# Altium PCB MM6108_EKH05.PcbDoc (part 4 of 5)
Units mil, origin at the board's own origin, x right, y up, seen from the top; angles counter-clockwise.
Board outline 6023.62 x 3425.2 mil, 4 copper layers (Top Layer, Ground Plane, Middle Layer, Bottom Layer), stack 76.15 mil thick; 212 components, 163 nets, 749 pads, 1477 vias.
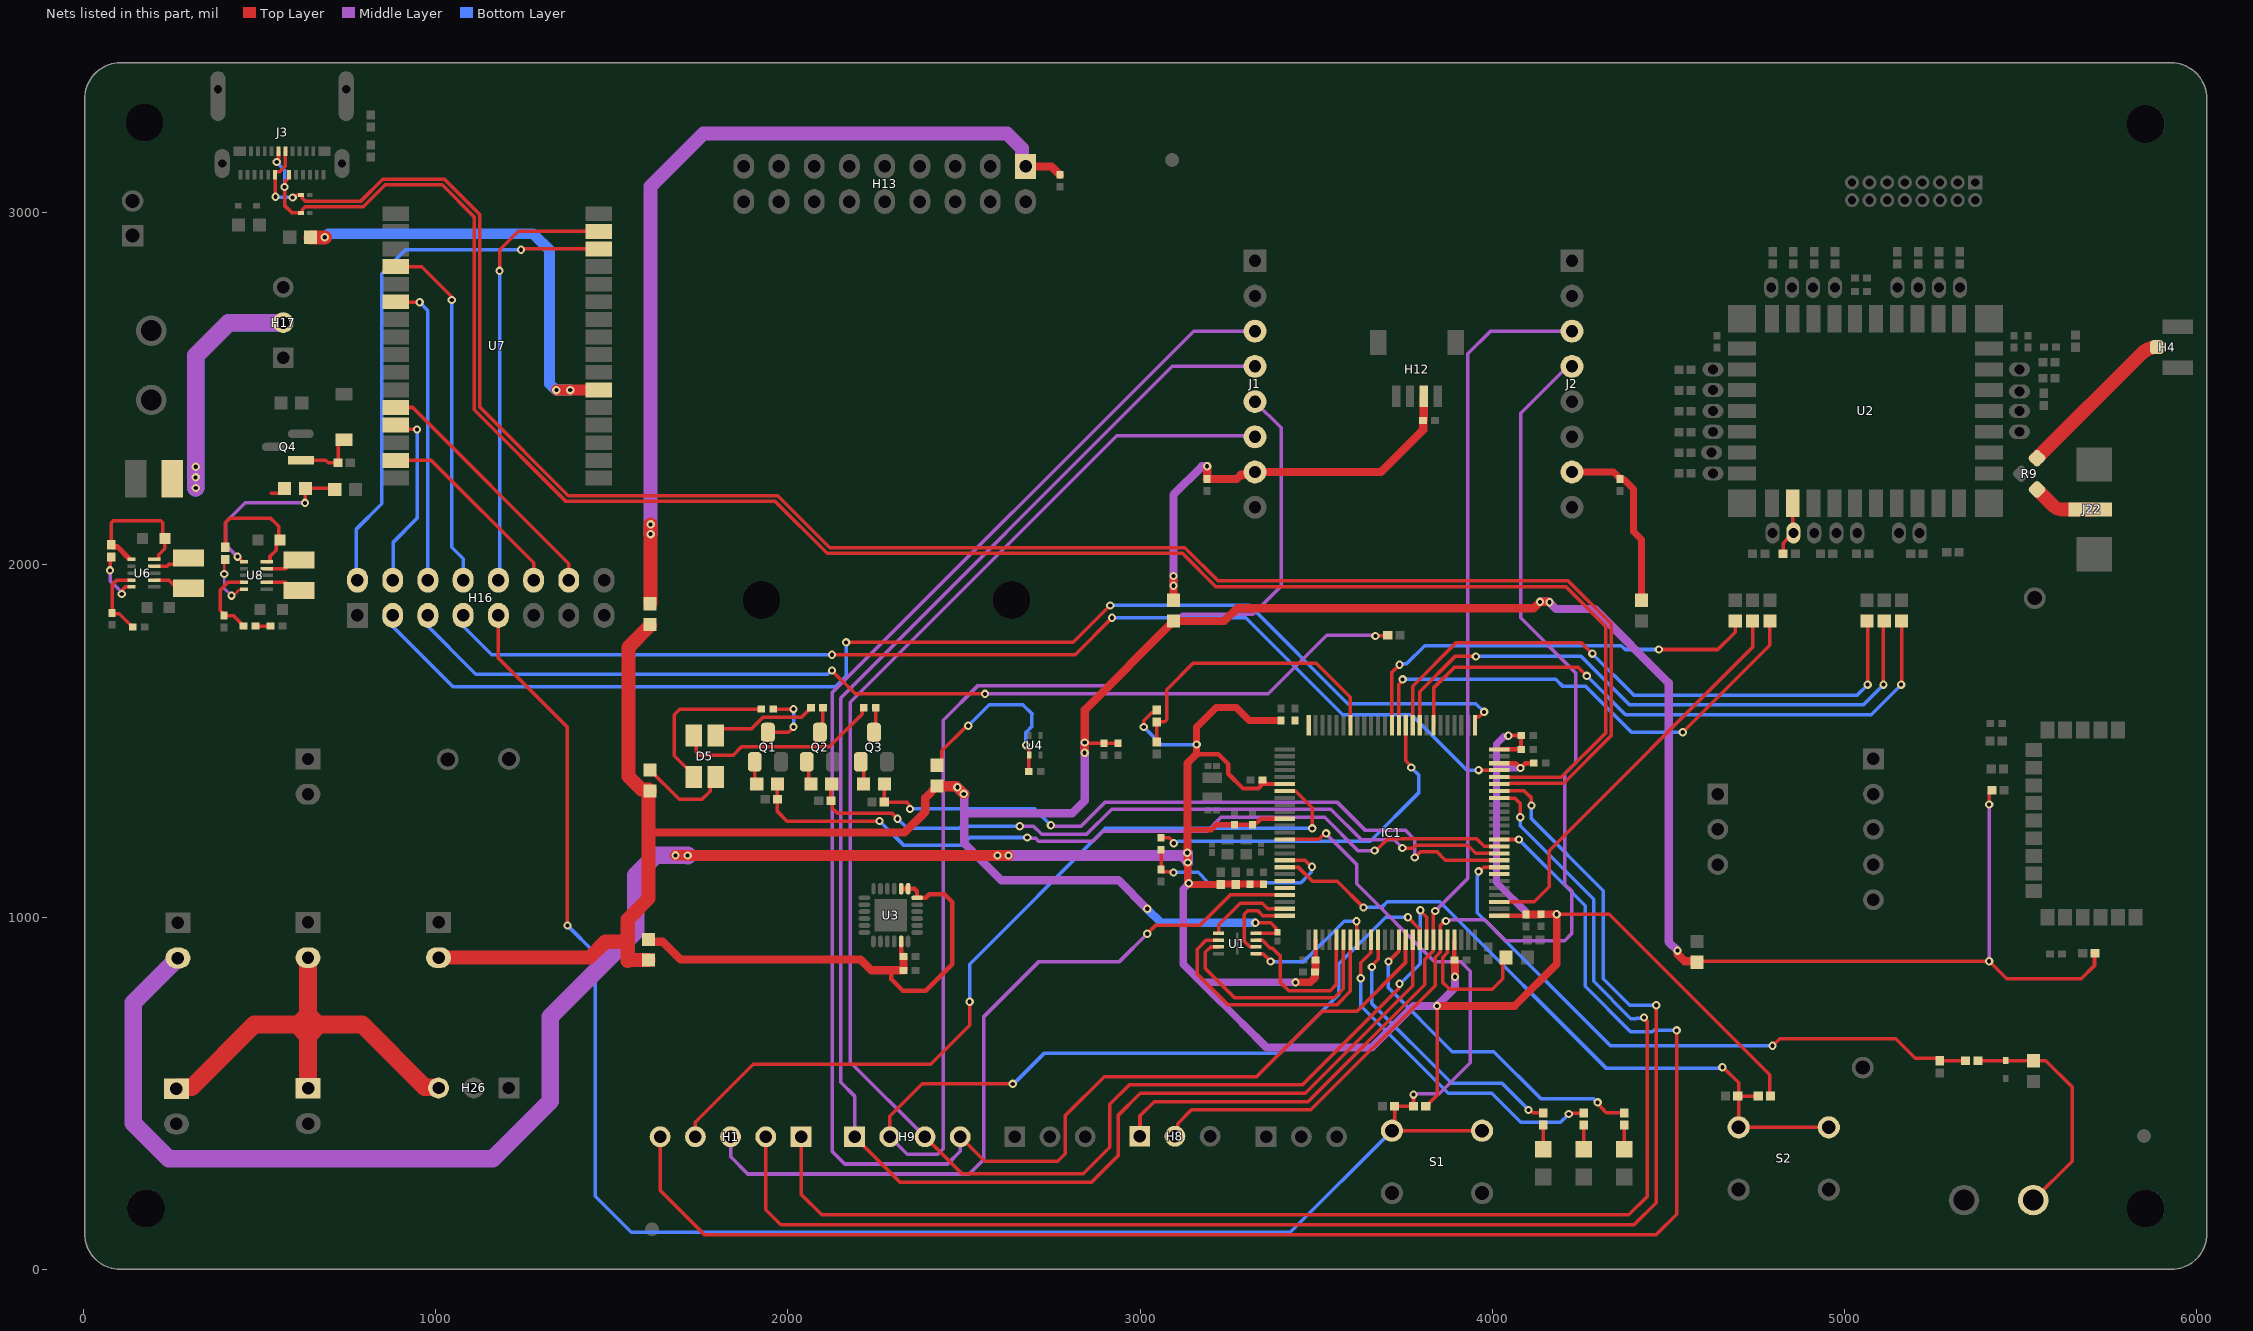
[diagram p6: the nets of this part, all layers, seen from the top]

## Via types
v1: diameter 23.62, hole 11.81, Top Layer to Bottom Layer, tented both sides, 1477 vias

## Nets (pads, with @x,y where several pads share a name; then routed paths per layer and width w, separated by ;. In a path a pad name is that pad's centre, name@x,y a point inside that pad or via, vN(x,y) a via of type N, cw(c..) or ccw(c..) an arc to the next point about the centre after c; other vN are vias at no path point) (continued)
NetC39_2: C39.2 R54.2 U4.3 | length 543.2
  Top Layer w10: R54.2@2423.23,1431.1 2436.63,1444.5 2436.63,1472.06 2501.06,1536.5 2501.31,1536.5 2508.12,1543.31 v1(2511.81,1543.31) ; v1(2675.64,1488.44) 2675.64,1484.75 2684.13,1476.26 2684.13,1461.54 U4.3@2685.04,1460.63 2683.46,1459.06 C39.2@2683.46,1413.39
  Bottom Layer w10: v1(2511.81,1543.31) 2571.77,1603.27 2666.61,1603.27 2692.79,1577.08 2692.79,1576.91 2692.66,1576.78 2692.66,1541.61 2685,1533.95 2685,1533.64 2675.64,1524.28 v1(2675.64,1488.44)
NetC45_2: C45.2 H13.1 R55.2 | length 2506.4
  Top Layer w23.62: H13.1@2674.41,3131.5 2674.73,3131.17 2748.03,3131.17 C45.2@2771.65,3107.55
  Top Layer w40: v1(1610,2115) 1610,1891.97 R55.2@1610.24,1891.73
  Middle Layer w40: v1(1610,2087.44) v1(1610,2115) 1610,3074.57 1759.84,3224.41 1908.23,3224.41 2622.05,3224.41 2664.88,3181.57 2664.88,3141.02 H13.1@2674.41,3131.5
NetC46_2: C46.2 C48.2 H12.3 J1.7 R61.2 | length 1261.6
  Top Layer w23.62: R61.2@3094.49,1899.61 v1(3094.49,1940.94) v1(3094.49,1968.5) ; v1(3190,2280) 3190,2244.8 C46.2@3188.98,2243.77 3273.77,2243.77 3285.67,2255.67 3317.67,2255.67 J1.7@3325.59,2263.58 3683.58,2263.58 3803,2383 C48.2@3803,2410 3805.28,2412.28 H12.3@3805.28,2479
  Middle Layer w23.62: v1(3094.49,1940.94) v1(3094.49,1968.5) 3094.49,2199.49 3175,2280 v1(3190,2280)
NetC47_2: C47.2 J2.7 R60.1 | length 521.1
  Top Layer w20: J2.7@4225.59,2263.58 4343.39,2263.58 4362.2,2244.77 C47.2@4362.2,2243.77 4362.2,2242.77 4372.83,2242.77 4400,2215.6 4400,2095 4423.23,2071.77 R60.1@4423.23,1899.61
NetD1_A: D1.A R4.2 | length 68.9
  Top Layer w10: D1.A@4374.02,340.94 R4.2@4374.02,409.84
NetD2_A: D2.A R5.2 | length 68.9
  Top Layer w10: D2.A@4258.86,340.94 R5.2@4258.86,409.84
NetD3_A: D3.A R6.2 | length 68.9
  Top Layer w10: D3.A@4143.7,340.94 R6.2@4143.7,409.84
NetD4_K: D4.K H11.2 R51.1 R52.1 | length 665.2
  Top Layer w10: R51.1@5377.95,592.52 D4.K@5456.69,592.52 R52.1@5535.43,592.52 5570.87,592.52 5645.67,517.72 5645.67,307.09 H11.2@5535.43,196.85
NetD5_1: D5.1 R59.1 | length 454.1
  Top Layer w10: D5.1@1732.28,1397.65 1732.28,1405.53 1713.65,1424.15 1711.64,1424.15 1677.17,1458.62 1677.17,1574.8 1692.91,1590.55 R59.1@1923.62,1590.55
NetD5_2: D5.2 R56.2 | length 280.6
  Top Layer w10: R56.2@1621.97,1431.02 R56.2@1608.27,1417.32 1690.94,1334.65 1755.91,1334.65 1778.92,1357.67 1778.92,1381.31 D5.2@1795.27,1397.65
NetD5_3: D5.3 R58.1 | length 303.3
  Top Layer w10: D5.3@1795.27,1515.76 1795.27,1516.81 1813.89,1535.43 1896.96,1535.43 1928.45,1566.93 2037.8,1566.93 R58.1@2065.35,1594.49
NetD5_4: D5.4 R57.1 | length 591.7
  Top Layer w10: D5.4@1732.28,1515.76 1740,1508.04 1740,1470 1750,1460 1844.66,1460 1868.14,1483.48 2117.34,1483.48 2210.71,1576.85 2210.71,1589.91 R57.1@2215.28,1594.49
NetD6_A: D6.A Q4.1 R75.1 | length 184.2
  Top Layer w10: Q4.1@616.82,2297.6 687.4,2297.6 695,2290 R75.1@722.68,2290 722.68,2342.52 735.59,2355.43 D6.A@740,2355.43
NetH4_1: H4.1 R9.C | length 467.9
  Top Layer w39: R9.C@5545.89,2303.03 5843.39,2600.53 cw(c5885.83,2558.1) H4.1@5885.83,2618.11
NetH16_2: H16.2 U7.30 | length 1548.6
  Top Layer w10: v1(1242.26,2894.52) 1244.59,2896.85 U7.30@1462.76,2896.85
  Bottom Layer w10: H16.2@775,1953.09 775,2101.77 846.46,2173.23 846.46,2826.77 914.21,2894.52 v1(1242.26,2894.52)
NetH16_4: H16.4 U7.13 | length 522.2
  Top Layer w10: U7.13@886.38,2396.85 898.71,2384.52 v1(946.95,2384.52)
  Bottom Layer w10: H16.4@877.76,1956.69 880,1958.94 880,2065 946.95,2131.95 v1(946.95,2384.52)
NetH16_5: H16.5 R3.1 | length 2924.2
  Top Layer w10: v1(2125,1700) 2191.14,1633.86 v1(2559.06,1633.86) ; v1(3667.43,1798.25) 3668.3,1799.13 3701.8,1799.13 R3.1@3702.68,1800
  Middle Layer w10: v1(2559.06,1633.86) 3363.86,1633.86 3530,1800 3665.68,1800 v1(3667.43,1798.25)
  Bottom Layer w10: H16.5@952.76,1856.69 952.76,1850.79 965.26,1838.29 1113.54,1690 2112.33,1690 2122.33,1700 v1(2125,1700)
NetH16_6: H16.6 U7.6 | length 867
  Top Layer w10: U7.6@886.38,2746.85 887.71,2745.51 v1(954.28,2745.51)
  Bottom Layer w10: v1(954.28,2745.51) 977.76,2722.04 H16.6@977.76,1956.69
NetH16_8: H16.8 U7.4 | length 1017.4
  Top Layer w10: U7.4@886.38,2846.85 960.24,2846.85 1047.24,2759.84 v1@1047.24,2748.03
  Bottom Layer w10: v1(1045.28,2751.97) 1045.28,2049.72 1077.76,2017.24 H16.8@1077.76,1956.69
NetH16_10: H16.10 U7.31 | length 1242.1
  Top Layer w10: v1(1181.1,2834.65) 1182.19,2835.73 1182.19,2894.78 1234.25,2946.85 U7.31@1462.76,2946.85
  Bottom Layer w10: H16.10@1177.76,1956.69 1181.1,1960.04 v1(1181.1,2834.65)
NetH16_12: H16.12 U7.15 | length 561
  Top Layer w10: U7.15@886.38,2296.85 986.61,2296.85 1277.76,2005.71 H16.12@1277.76,1956.69
NetH16_14: H16.14 U7.12 | length 721.8
  Top Layer w10: U7.12@886.38,2446.85 934.35,2446.85 1377.76,2003.45 H16.14@1377.76,1956.69
NetIC1_46: IC1.46 L1.2 | length 382.7
  Top Layer w10: IC1.46@3872.05,935.51 3872.05,898.81 3858.27,885.04 3858.27,814.96 3878.23,795 3999.72,795 4029.53,824.8 4029.53,877.36 L1.2@4037.99,885.83
NetJ22_1: J22.1 R9.B | length 173.1
  Top Layer w39: R9.B@5545.89,2213.95 5546.02,2213.82 5590.97,2168.87 ccw(c5618.52,2196.48) 5618.52,2157.48 J22.1@5697.25,2157.48
NetL3_1: L3.1 U6.9 | length 68.1
  Top Layer w10: U6.9@214.06,1996.38 237.56,1996.38 242.48,2001.3 L3.1@280.08,2001.3
NetL3_2: L3.2 U6.7 | length 84
  Top Layer w10: U6.7@201.34,1957.01 241.69,1957.01 254.49,1944.21 L3.2@280.08,1944.21
NetL4_1: L4.1 U8.9 | length 92.3
  Top Layer w10: U8.9@520.43,1989.69 574.57,1989.68 583.43,1998.54 L4.1@609.02,1998.54
NetL4_2: L4.2 U8.7 | length 92.3
  Top Layer w10: U8.7@520.43,1950.32 574.57,1950.32 583.43,1941.46 L4.2@609.02,1941.46
NetQ1_D: Q1.D R59.2 | length 187.7
  Top Layer w10: Q1.D@1942.93,1524.37 2000.75,1524.37 2008.94,1532.56 2008.94,1532.81 2015.75,1539.62 v1(2015.75,1540.12) ; R59.2@1958.27,1590.55 v1(2015.75,1590.55)
  Bottom Layer w10: v1(2015.75,1540.12) v1(2015.75,1590.55)
NetQ1_G: Q1.G R62.2 | length 65.4
  Top Layer w10: Q1.G@1905.53,1440.94 1905.53,1383.84 R62.2@1911.42,1377.95
NetQ2_D: Q2.D R58.2 | length 73.7
  Top Layer w10: Q2.D@2090.55,1524.37 2099.21,1533.03 R58.2@2099.21,1594.49
NetQ2_G: Q2.G R63.2 | length 70.5
  Top Layer w10: R63.2@2059.06,1383.86 Q2.G@2059.06,1435.04
  Top Layer w23.62: Q2.G@2053.15,1440.94 Q2.G@2059.06,1435.04 ; R63.2@2059.06,1383.86 R63.2@2064.96,1377.95 ; R63.2@2067.02,1379.83 R63.2@2068.9,1377.95
NetQ3_D: Q3.D R57.2 | length 72.4
  Top Layer w10: Q3.D@2244.11,1524.37 2249.61,1529.87 R57.2@2249.61,1594.49
NetQ3_G: Q3.G R64.2 | length 74.6
  Top Layer w10: Q3.G@2206.71,1440.94 2214.57,1433.09 R64.2@2214.57,1377.95 R64.2@2220.47,1372.05
NetR10_1: R10.1 R12.1 U8.1 | length 525.6
  Top Layer w10: v1(629,2176) 629,2216.16 R10.1@630.01,2217.17 704.3,2217.17 R12.1@704.47,2217 ; U8.1@448.66,2009.45 U8.1@448.66,2011.34 ; U8.1@448.66,2009.45 U8.1@448.74,2009.37 ; U8.1@448.66,2009.45 U8.1@448.74,2009.37 ; U8.1@448.66,2009.45 U8.1@448.66,2011.34 ; U8.1@448.66,2011.34 437,2023 U8.1@448.66,2011.34 ; U8.1@448.74,2009.37 U8.1@455.47,2009.37 U8.1@448.74,2009.37
  Middle Layer w10: v1(437.24,2023.54) 404,2056.78 404,2121 459,2176 v1(629,2176)
NetR30_2: pad.31@4854.33,2090.55 R30.2 U2.10 | length 157.7
  Top Layer w10: R30.2@4825.2,2031.5 4825.2,2061.42 4838.59,2074.81 4840.47,2074.81 4854.33,2088.67 pad.31@4854.33,2090.55 4852.36,2092.52 U2.10@4852.36,2175.2
NetR68_2: R68.2 U6.5 | length 156.7
  Top Layer w10: v1(75.35,1984.57) 75.35,2018.43 R68.2@79.29,2022.36 ; v1(108.82,1917.64) 111.43,1920.24 111.43,1929.98 118.77,1937.32 U6.5@129.57,1937.32
  Middle Layer w10: v1(75.35,1984.57) 75.35,1954.79 108.18,1921.96 v1@108.18,1915.46
NetR71_2: R71.2 R72.1 U6.4 | length 216.3
  Top Layer w10: U6.4@136.38,1957.01 95.04,1957.01 81.26,1943.23 R72.1@81.26,1863.77 84.15,1860.89 102.02,1860.89 132.95,1829.96 134.13,1829.96 139.76,1824.33 R71.2@139.77,1823.15
NetR73_1: R73.1 U7.22 | length 1268.2
  Top Layer w31: v1(1342.52,2496.06) v1(1381.89,2496.06) 1461.97,2496.06 U7.22@1462.76,2496.85
  Top Layer w40: R73.1@644.53,2930 v1(685,2930)
  Bottom Layer w31: v1(685,2930) 695,2940 1276.54,2940 1322.83,2893.7 1322.83,2514.22 1340.99,2496.06 v1(1342.52,2496.06) v1(1381.89,2496.06)
NetR74_2: R74.2 U8.5 | length 155.3
  Top Layer w8: v1(399.49,1974.14) 399.49,2012.83 R74.2@402.32,2015.67 ; v1(420.04,1912.84) 423.03,1915.83 429.05,1915.83 442.93,1929.71 454.55,1929.71 U8.5@455.47,1930.63
  Middle Layer w8: v1(399.49,1974.14) 399.49,1933.39 v1(420.04,1912.84)
NetR76_2: R76.2 R84.1 | length 42.9
  Top Layer w10: R84.1@488.22,1826.23 R76.2@531.17,1826.23
NetR77_1: R77.1 R84.2 U8.4 | length 226.6
  Top Layer w10: U8.4@455.47,1950.32 410.27,1950.32 388.54,1928.59 388.54,1870.79 397.48,1861.86 397.48,1860.67 403.11,1855.04 404.29,1855.04 426.65,1855.04 448.58,1833.12 448.58,1831.86 R84.2@459.41,1821.03
PA0: H1.3 IC1.22 | length 2215.6
  Top Layer w10: v1(3019.69,952.76) 3043.31,976.38 3169.29,976.38 3255.91,1062.99 IC1.22@3409.92,1062.99
  Middle Layer w10: H1.3@1837.01,376.69 1837.01,320.09 1886.26,270.84 2514.94,270.84 2555.12,311.02 2555.12,716.54 2712.6,874.02 2940.94,874.02 v1(3019.69,952.76)
PA9: H1.1 IC1.68 | length 3968
  Top Layer w10: H1.1@2037.01,376.69 2037.01,213.61 2095.56,155.06 4387.34,155.06 4440,207.72 4440,702.33 4430,712.33 v1(4430,715) ; IC1.68@4019.21,1338.58 4020.12,1337.68 4063.9,1337.68 4078.74,1322.83 v1@4078.74,1284.32
  Bottom Layer w10: v1(4078.74,1283.46) 4078.74,1259.84 4287.4,1051.18 4287.4,817.6 4392.95,712.05 4408.19,712.05 4408.53,712.39 4427.39,712.39 v1(4430,715)
PA10: H1.2 IC1.69 | length 4217.7
  Top Layer w10: H1.2@1937.01,376.69 1937.01,169.29 1979.38,126.92 4401.92,126.92 4464.54,189.54 4464.54,749.54 v1(4465,750) ; IC1.69@4019.21,1358.27 4090.55,1358.27 4110.63,1338.19 v1(4110.63,1316.83)
  Bottom Layer w10: v1(4110.63,1316.83) 4110.63,1279.13 4314.96,1074.8 4314.96,825.04 4390,750 v1(4465,750)
PC13: H1.4 IC1.7 | length 2396.4
  Top Layer w10: H1.4@1737.01,376.69 1737.01,418.11 1901.57,582.68 2405.51,582.68 2515.75,692.91 v1(2515.75,759.84) ; IC1.7@3409.92,1358.27 3410.83,1357.36 3441.64,1357.36 3488.19,1310.81 v1(3488.19,1251.97)
  Bottom Layer w10: v1(2515.75,759.84) 2515.75,866.35 2901.37,1251.97 v1(3488.19,1251.97)
PD10: IC1.57
PD11: C36.1 IC1.58 R51.2 | length 1758.7
  Top Layer w10: v1(3960.63,1129.92) 3963.37,1129.92 3975.18,1141.73 IC1.58@4019.21,1141.73 ; v1(4795,635) 4815,655 5144.62,655 5199.8,599.82 5262.48,599.82 C36.1@5269.69,592.61 ; C36.1@5269.69,592.52 R51.2@5343.31,592.52
  Bottom Layer w10: v1(3960.63,1129.92) 3958.02,1127.31 3958.02,1118.06 3957.21,1117.25 3957.21,1012.79 4335,635 v1(4795,635)
PD15: H1.5 IC1.62 | length 4524.8
  Top Layer w10: H1.5@1637.01,400.68 1637.01,224.1 1762.18,98.92 4465.06,98.92 4522.81,156.67 v1(4522.81,678.54) ; IC1.62@4019.21,1220.47 v1(4074.8,1220.47)
  Bottom Layer w10: v1(4074.8,1220.47) 4262.97,1032.31 4262.97,803.96 4391.93,675 4453.76,675 4457.3,678.54 v1(4522.81,678.54)
PH3-BOOT0: IC1.94 R7.1 R8.1 | length 832.9
  Top Layer w10: R8.1@3047.24,1509.45 R7.1@3047.24,1554.33 ; R7.1@3047.24,1553.54 R7.1@3047.24,1554.33 ; IC1.94@3596.46,1544.8 3596.46,1624.02 3500,1720.47 3149.61,1720.47 3074.8,1645.67 3074.8,1560.19 3068.95,1554.33 R7.1@3047.24,1554.33
SDMMC2_CLK: IC1.87 R31.1 | length 1409.8
  Top Layer w10: IC1.87@3734.25,1544.8 3734.25,1660.57 3745,1671.31 v1(3745,1675) ; v1(4540,1525) 4787.4,1772.4 R31.1@4787.4,1840.55
  Bottom Layer w10: v1(3745,1675) 4180,1675 4200.12,1654.88 4264.85,1654.88 4394.73,1525 v1(4540,1525)
SDMMC2_CMD: IC1.88 R32.1 | length 1212.4
  Top Layer w10: IC1.88@3714.57,1544.8 3714.57,1694.88 v1(3736.22,1716.54) ; v1(4472.44,1759.84) 4639.84,1759.84 4688.98,1808.98 R32.1@4688.98,1840.55
  Bottom Layer w10: v1(3736.22,1716.54) 3738.83,1719.14 3755.93,1719.14 3807.63,1770.84 4365.89,1770.84 4376.89,1759.84 v1(4472.44,1759.84)
SDMMC2_D0: IC1.53 R33.1 | length 1153
  Top Layer w10: IC1.53@4019.21,1043.31 4118.11,1043.31 4161.17,1086.36 4161.17,1188.72 4738.19,1765.75 R33.1@4738.19,1840.55
SENSORS_SPI_CLK: H9.1 IC1.41 J1.4 | length 4893.7
  Top Layer w10: H9.1@2188.88,376.69 2317.54,248.03 2862.2,248.03 2937.01,322.83 2937.01,437.01 3000,500 3468.5,500 3773.62,805.12 IC1.41@3773.62,935.51
  Middle Layer w10: H9.1@2188.88,376.69 2188.88,492.22 2149.61,531.5 2149.61,1622.05 3091.14,2563.58 J1.4@3325.59,2563.58
SENSORS_SPI_CS: H9.4 IC1.40 J1.3 | length 5016.4
  Top Layer w10: H9.4@2488.88,376.69 2558.48,307.09 2765.8,307.09 2781.54,322.83 2787.4,328.69 2787.4,437.01 2897.64,547.24 3330.04,547.24 3515.08,732.28 3614.17,732.28 3753.03,871.14 3753.03,934.61 IC1.40@3753.94,935.51
  Middle Layer w10: H9.4@2488.88,376.69 2488.88,335.33 2452.76,299.21 2161.42,299.21 2125.98,334.65 2125.98,1637.8 3151.77,2663.58 J1.3@3325.59,2663.58
SENSORS_SPI_MISO: H9.2 IC1.42 J1.5 | length 4954.8
  Top Layer w10: H9.2@2288.88,376.69 2288.88,434.55 2381.12,526.79 v1(2638.08,526.79) ; v1(3759.7,999.66) 3759.97,999.66 3792.4,967.23 3792.4,936.42 IC1.42@3793.31,935.51
  Middle Layer w10: H9.2@2288.88,376.69 2338.8,326.77 2425.2,326.77 2440.94,342.52 2440.94,1559.06 2539.37,1657.48 2917.32,1657.48 3119.84,1860 3320,1860 3400,1940 3400,2389.17 J1.5@3325.59,2463.58
  Bottom Layer w10: v1@2641.73,527.56 2728.35,614.17 3397.64,614.17 3562.99,779.53 3562.99,866.14 3696.51,999.66 v1(3759.7,999.66)
SENSORS_SPI_MOSI: H9.3 IC1.43 J1.6 | length 4801.9
  Top Layer w10: H9.3@2388.88,376.69 2493.92,271.65 2838.58,271.65 2913.39,346.46 2913.39,468.39 2968.62,523.62 3459.87,523.62 3733.61,797.37 3733.61,808.42 v1(3736.22,811.02) ; v1(3795.28,1019.68) 3795.28,1017.2 3812.99,999.48 IC1.43@3812.99,935.51
  Middle Layer w10: H9.3@2388.88,376.69 2177.17,588.41 2177.17,1610.24 2933.07,2366.14 3323.03,2366.14 J1.6@3325.59,2363.58
  Bottom Layer w10: v1(3736.22,811.02) 3738.41,811.02 3795.28,867.89 v1(3795.28,1019.68)
SENSORS_UART_RX: H8.1 IC1.44 J2.3 | length 3186
  Top Layer w10: H8.1@2998.43,377.95 2999.3,378.83 2999.3,436.31 3039.37,476.38 3476.15,476.38 3807.89,808.12 3807.89,879.92 3831.77,903.79 3831.77,934.61 IC1.44@3832.68,935.51 3831.8,936.39 3831.8,1008.9 3837.51,1014.62 v1(3837.51,1017.31)
  Middle Layer w10: v1(3837.51,1017.31) 3930,1109.79 3930,2599.29 3994.29,2663.58 J2.3@4225.59,2663.58
SENSORS_UART_TX: H8.2 IC1.45 J2.4 | length 3290.3
  Top Layer w10: H8.2@3098.43,377.95 3106.13,385.66 3106.13,413.22 3145.67,452.76 3484.25,452.76 3837,805.5 3837,886.39 3851.46,900.85 3851.46,934.61 IC1.45@3852.36,935.51 3852.36,976.85 3864.51,989 v1(3867.6,989)
  Middle Layer w10: v1(3867.6,989) 3870.2,991.61 3879.75,991.61 3880.27,992.13 3977.87,992.13 4036.93,933.07 4204.72,933.07 4224.41,952.76 4224.41,1074.8 4205.54,1093.68 4205.54,1407.26 4236.22,1437.94 4236.22,1693.3 4080,1849.52 4080,2430.39 4213.19,2563.58 J2.4@4225.59,2563.58 J2.4@4231.69,2563.58
STATUS_LED_B: IC1.36 R6.1 | length 803.6
  Top Layer w10: v1(3657.48,858.27) 3657.48,861.95 3676.1,880.58 3676.1,934.61 IC1.36@3675.2,935.51 ; v1(4102.36,452.76) 4106.05,452.76 4114.32,444.49 R6.1@4143.7,444.49
  Bottom Layer w10: v1(3657.48,858.27) 3657.48,754.79 3884.21,528.06 4027.06,528.06 v1(4102.36,452.76)
STATUS_LED_G: IC1.35 R5.1 | length 980.8
  Top Layer w10: v1(3625.98,826.77) 3625.98,870.08 3654.61,898.7 3654.61,934.61 IC1.35@3655.51,935.51 ; v1(4216.54,440.94) 4218.31,442.72 4257.09,442.72 R5.1@4258.86,444.49
  Bottom Layer w10: v1(3625.98,826.77) 3625.98,748.03 3874.02,500 3997.87,500 4080.55,417.32 4192.91,417.32 v1(4216.54,440.94)
STATUS_LED_R: IC1.39 R4.1 | length 967.7
  Top Layer w10: v1(3704.72,874.02) 3733.35,902.64 3733.35,934.61 IC1.39@3734.25,935.51 ; v1(4298.56,474.16) 4298.56,470.48 4315.31,453.73 4315.31,452.4 4323.23,444.49 R4.1@4374.02,444.49
  Bottom Layer w10: v1(3704.72,874.02) 3704.72,799.21 3885.83,618.11 4003.94,618.11 4137.05,485 4285.9,485 4296.73,474.16 v1(4298.56,474.16)
STM_NRST: C19.1 H16.9 IC1.14 R2.2 S1.1 S1.2 | length 5799
  Top Layer w10: H16.9@1177.76,1865.03 1177.76,1735.63 1374.02,1539.37 v1(1374.02,976.38) ; IC1.14@3409.92,1220.47 3410.83,1221.38 3507.53,1221.38 3523.96,1237.81 v1(3527.65,1237.81) ; v1(3775.59,496.06) 3775.79,495.87 3775.79,462.8 R2.2@3775.98,462.6 C19.1@3722.05,462.6 3722.05,401.18 S1.2@3714.57,393.7 S1.1@3970.47,393.7
  Middle Layer w10: v1(3527.65,1237.81) 3527.65,1236.13 3614.17,1149.61 3614.17,1094.49 3834.65,874.02 3909.45,874.02 3937.01,846.46 3937.01,586.61 3849.06,498.67 3778.2,498.67 v1(3775.59,496.06)
  Bottom Layer w10: v1(1374.02,976.38) 1452.76,897.64 1452.76,207.24 1554.62,105.38 3426.25,105.38 S1.2@3714.57,393.7
STM_QSPI_CLK: IC1.25 U1.6 | length 240.6
  Top Layer w10: U1.6@3328.54,915.35 3312,915.35 3295.28,932.08 3295.28,1007.79 3305.45,1017.97 3334.2,1017.97 3347.98,1004.19 3409.67,1004.19 IC1.25@3409.92,1003.94
STM_QSPI_CS: IC1.24 U1.1 | length 242.8
  Top Layer w10: U1.1@3222.64,954.72 3222.64,978.54 3283.46,1039.37 3346.46,1039.37 3362.2,1023.62 IC1.24@3409.92,1023.62
STM_QSPI_IO0: IC1.33 U1.5 | length 394.5
  Top Layer w10: U1.5@3328.54,895.67 3348.43,895.67 v1(3370.08,874.02) ; v1(3614.17,988.19) 3615.24,987.13 3615.24,936.42 IC1.33@3616.14,935.51
  Bottom Layer w10: v1@3370.94,874.02 3464.57,874.02 3578.74,988.19 v1(3614.17,988.19)
STM_QSPI_IO1: IC1.32 U1.2 | length 775.1
  Top Layer w10: U1.2@3222.64,935.04 3222.56,934.96 3187.22,934.96 3161.42,909.16 3161.42,838.58 3248.03,751.97 3559.06,751.97 3596.46,789.37 IC1.32@3596.46,935.51
STM_QSPI_IO2: IC1.31 U1.3 | length 664.6
  Top Layer w10: 3206.1,915.35 3206.02,915.28 ; U1.3@3222.64,915.35 3222.56,915.28 3206.02,915.28 ; IC1.31@3576.77,935.51 3576.77,797.24 3551.18,771.65 3267.72,771.65 3185.04,854.33 3185.04,900.04 3200.28,915.28 3206.02,915.28
STM_QSPI_IO3: IC1.30 U1.7 | length 465.7
  Top Layer w10: U1.7@3328.54,935.04 3328.62,934.96 3345.94,934.96 3369.07,911.83 3375.57,911.83 3396.88,890.52 3396.88,815.71 3421.26,791.34 3539.37,791.34 3557.09,809.06 IC1.30@3557.09,935.51
STM_SPI2_CLK: IC1.82 R41.2 | length 1729.1
  Top Layer w10: IC1.82@3832.68,1544.8 3832.7,1650.67 3890.94,1708.91 4243.84,1708.91 v1(4267.72,1685.04) ; v1(5160,1660) 5161.42,1661.42 R41.2@5161.42,1840.55
  Bottom Layer w10: v1(4267.72,1685.04) 4377.76,1575 5075,1575 v1(5160,1660)
STM_SPI2_MISO: IC1.84 R43.2 | length 1715.6
  Top Layer w10: IC1.84@3793.31,1544.8 3793.33,1639.78 3893.7,1740.16 v1(3952.76,1740.16) ; v1(5110,1660) 5110,1838.35 R43.2@5112.2,1840.55
  Bottom Layer w10: v1(3952.76,1740.16) 4251.97,1740.16 4389.76,1602.36 5052.36,1602.36 v1(5110,1660)
STM_SPI2_MOSI: IC1.85 R42.2 | length 1709.2
  Top Layer w10: IC1.85@3773.64,1544.82 3773.64,1655.53 3897.64,1779.53 4251.97,1779.53 v1(4283.46,1748.03) ; R42.2@5062.99,1840.55 5065,1838.54 v1(5065,1660)
  Bottom Layer w10: v1(4283.46,1748.03) 4401.57,1629.92 5034.92,1629.92 v1(5065,1660)
SWD_CLK: H16.3 IC1.76 | length 3542.1
  Top Layer w10: v1(2165,1780) 2810,1780 v1(2915,1885) ; IC1.76@3950.79,1544.8 3950.79,1567.93 3951.69,1568.84 3962.54,1568.84 v1(3976.38,1582.68)
  Bottom Layer w10: H16.3@852.76,1856.69 852.76,1850.79 1049.17,1654.38 2134.38,1654.38 2165,1685 v1(2165,1780) ; v1(2915,1885) 3310,1885 3588.7,1606.3 3952.76,1606.3 v1(3976.38,1582.68)
SWD_DIO: H16.7 IC1.72 | length 3231.3
  Top Layer w10: v1(2125,1745) 2815,1745 v1(2920,1850) ; v1(3960.63,1417.32) IC1.72@4019.21,1417.32
  Bottom Layer w10: H16.7@1053.94,1849.61 1158.54,1745 v1(2125,1745) ; v1(2920,1850) 3300,1850 3575.2,1574.8 3770.2,1574.8 3927.68,1417.32 v1(3960.63,1417.32)
TIM4_CH1: IC1.59 R64.1 R67.2 | length 1971.9
  Top Layer w10: R64.1@2273.62,1377.95 2273.23,1377.56 R67.2@2273.23,1326.77 2336.51,1326.77 2343.85,1319.43 2343.85,1309.69 v1(2346.46,1307.09) ; v1(3779.53,1169.29) 3796.48,1186.24 3841.32,1186.24 3866.14,1161.42 IC1.59@4019.21,1161.42
  Middle Layer w10: v1(2746.32,1260.74) 2748.48,1258.59 2832.61,1258.59 2900.79,1326.77 3558.42,1326.77 3637.9,1247.29 3752.4,1247.29 3779.53,1220.16 v1(3779.53,1169.29)
  Bottom Layer w10: v1(2346.46,1307.09) 2699.98,1307.09 v1(2746.32,1260.74)
TIM4_CH2: IC1.60 R63.1 R66.2 | length 2088.7
  Top Layer w10: R63.1@2124.02,1377.95 2122.05,1375.98 R66.2@2122.05,1330.71 2125.64,1327.12 2125.64,1309.36 2139.47,1295.53 2295.02,1295.53 v1(2311.02,1279.53) ; v1(3744.09,1196.19) 3775.19,1196.19 3783,1204 3929.86,1204 3952.76,1181.1 IC1.60@4019.21,1181.1
  Middle Layer w10: v1(2657.88,1258.19) 2696.81,1258.19 2720,1235 2847.59,1235 2918.86,1306.28 3541.01,1306.28 3627.95,1219.34 3721.61,1219.34 3744.09,1196.85 v1(3744.09,1196.19)
  Bottom Layer w10: v1(2311.02,1279.53) 2338.58,1251.97 2485.93,1251.97 2492.16,1258.19 v1(2657.88,1258.19)
TIM4_CH3: IC1.61 R62.1 R65.2 | length 2270
  Top Layer w10: R62.1@1970.47,1377.95 1970.08,1377.56 R65.2@1970.08,1334.65 1970.08,1299.92 1997.28,1272.72 v1(2259.84,1272.72) ; v1(3665.35,1188.98) 3669.04,1188.98 3675.85,1195.79 3676.1,1195.79 3702.31,1222 3955.17,1222 3976.38,1200.79 IC1.61@4019.21,1200.79
  Middle Layer w10: v1(2679.43,1226.13) 2682.03,1223.52 2702.95,1223.52 2711.24,1215.24 2865.88,1215.24 2894.87,1244.23 3189.87,1244.23 3229.11,1283.46 3523.62,1283.46 3618.11,1188.98 v1(3665.35,1188.98)
  Bottom Layer w10: v1(2259.84,1272.72) 2275.84,1256.72 2327.83,1204.72 2494.57,1204.72 2515.98,1226.13 v1(2679.43,1226.13)
USBC_N: D12.K IC1.70 J3.A7 J3.B7 | length 5507.1
  Top Layer w10: J3.A7@544.09,3107.48 544.09,3045.91 v1(545,3045) ; J3.A7@544.49,3116.14 557.11,3116.14 571.21,3130.24 573.23,3132.26 573.23,3174.02 J3.B7@573.62,3174.41 ; v1(593.75,3042.96) 597.37,3042.96 603.63,3049.21 617.01,3049.21 D12.K@617.8,3050 ; D12.K@620.16,3050 620.94,3049.21 620.94,3041.36 629.33,3032.98 787.98,3032.98 850,3095 1025,3095 1125.47,2994.53 1125.47,2447.26 1376.39,2196.34 1970.88,2196.34 2118.09,2049.12 3126.81,2049.12 3221.45,1954.49 4215.51,1954.49 4337.13,1832.87 4337.13,1515.57 4202.18,1380.61 4049.13,1380.61 4047.25,1378.74 4020,1378.74 IC1.70@4019.21,1377.95
  Bottom Layer w10: v1(545,3045) 546.02,3043.98 592.73,3043.98 v1(593.75,3042.96)
USBC_P: D11.K IC1.71 J3.A6 J3.B6 | length 5495.6
  Top Layer w10: J3.A6@583.46,3107.48 583.07,3107.09 583.07,3098.82 573.38,3089.13 573.38,3075.52 v1(570.82,3072.96) 570.82,3020.17 591.77,2999.22 D11.K@617.8,2999.22 ; D11.K@620.95,3000.01 620.95,3007.86 629.83,3016.74 794.7,3016.74 856.73,3078.76 1018.27,3078.76 1109.24,2987.8 1109.24,2440.53 1369.66,2180.1 1964.15,2180.1 2111.37,2032.89 3120.09,2032.89 3214.72,1938.26 4208.78,1938.26 4320.89,1826.14 4320.89,1522.29 4195.45,1396.85 4020,1396.85 IC1.71@4019.21,1397.64
  Top Layer w10.24: v1(548.41,3143.81) 548.41,3147.43 553.54,3152.56 553.54,3174.02 J3.B6@553.94,3174.41
  Bottom Layer w10: v1(548.41,3143.81) 548.41,3142.97 570.82,3120.56 v1(570.82,3072.96)
USER_BUTTON: C20.1 IC1.18 R1.2 S2.1 S2.2 | length 1995.1
  Top Layer w10: IC1.18@3409.92,1141.73 3410.52,1141.14 3449.42,1141.14 3488.88,1101.67 3559.75,1101.67 v1(3633.86,1027.56) ; v1(4652.66,573.92) 4654.43,573.92 4698.82,529.53 C20.1@4698.82,492.13 ; R1.2@4754.33,492.13 C20.1@4698.82,492.13 ; S2.1@4954.72,403.54 S2.2@4698.82,403.54 C20.1@4698.82,492.13
  Bottom Layer w10: v1(3633.86,1027.56) 3685.04,1027.56 3701.13,1043.65 3850.05,1043.65 4322.09,571.61 4650.35,571.61 v1(4652.66,573.92)
VDD_HALOW: H19.1 H21.2 H22.1 H26.3 | length 1377.8
  Top Layer w50: H19.1@265,513 269.53,517.53 307.53,517.53 485.4,695.4 609.79,695.4 637.35,722.96 ; 604.17,695.4 637.35,662.22 ; H22.1@637.35,517 637.35,662.22 ; H21.2@637.35,885 637.35,722.96 ; 670.53,695.4 637.35,662.22 ; H26.3@1007.88,515 1006.15,516.73 969.27,516.73 790.6,695.4 664.91,695.4 637.35,722.96 ; 637.35,662.22 637.35,722.96
VDD_MCU: C1.2 C2.2 C3.2 C4.2 C5.2 C6.2 C7.2 C8.2 C9.1 C10.2 C11.2 C14.2 C15.2 C16.2 C17.2 C18.2 C21.2 H24.2 IC1.6 IC1.11 IC1.20 IC1.21 IC1.27 IC1.47 IC1.51 IC1.73 IC1.75 IC1.100 R1.1 R2.1 R7.2 | length 10655.8
  Top Layer w10: v1(3010,1540) 3010,1557.05 3033.14,1580.2 3040.04,1580.2 3047.24,1587.4 R7.2@3047.24,1588.19 ; C18.2@3348.82,1094.49 C18.2@3350.39,1092.91 ; R2.1@3812.62,464.59 3842.52,494.49 v1(3842.52,748.03) ; v1(4045,1515) v1@4045.37,1515.37 ; C10.2@4080.73,1515.37 C10.2@4081.1,1515.75 ; v1(4182.14,1008.07) 4331.93,1008.07 4787.4,552.6 R1.1@4787.4,492.13
  Top Layer w12: 3159.45,1462.6 3222.4,1462.6 3250,1435 3250,1406.98 3291.98,1365 3335,1365 3342,1372 3342,1379 ; C3.2@3267.72,1262.2 C2.2@3318.9,1262.2 ; C2.2@3322.05,1259.06 3342.52,1279.53 IC1.11@3409.92,1279.53 ; IC1.6@3409.92,1377.95 3360.05,1377.95 ; C4.2@3497.31,874.02 3498.03,874.73 IC1.27@3498.03,935.51 ; C9.1@3891.73,878.35 IC1.47@3891.73,935.51 ; IC1.51@4019.21,1003.94 4019.31,1004.03 C6.2@4097.03,1004.03 ; IC1.73@4019.21,1437.01 4066.1,1437.01 v1(4079.67,1423.44) 4093.24,1437.01 C15.2@4116.86,1437.01 ; IC1.75@4019.21,1476.38 4081.1,1476.38 C10.2@4081.1,1515.75 ; v1@4045.37,1515.37 C10.2@4080.73,1515.37 ; 3342,1379 3342,1386 3346,1390 C1.2@3347,1390 3348,1390 3360.05,1377.95 ; 3342,1379 3343.05,1377.95 3360.05,1377.95
  Top Layer w15: 3133.86,1248.03 3202.18,1248.03 3216.35,1262.2 C3.2@3267.72,1262.2
  Top Layer w20: v1(3137.8,1096.12) 3138.78,1096.12 3141.98,1092.91 C17.2@3228.35,1092.91 ; 3159.45,1462.6 3159.45,1539.27 3214.81,1594.63 3272.78,1594.63 3309.41,1558 C14.2@3400,1558 ; C17.2@3232.28,1094.49 C18.2@3348.82,1094.49
  Top Layer w22: v1@3134.47,1155.53 3134.69,1155.75 3133.86,1156.58 3133.86,1248.03 3133.86,1437.01 3159.45,1462.6 ; v1(3135,1155) 3135,1099.35 3137.8,1096.56 v1(3137.8,1096.12) ; v1(3440.94,814.96) 3482.14,814.96 3496.02,828.85 C5.2@3496.02,844.11 3497.31,845.4 C4.2@3497.31,874.02 ; R2.1@3810.63,462.6 3811.42,462.6 3812.62,463.8 R2.1@3812.62,464.59 ; v1@3842.96,748.03 4063.03,748.03 4182.14,867.14 v1(4182.14,1008.07) ; C9.1@3892.45,877.95 3892.45,868.78 3893.7,867.53 v1(3893.7,830.71) ; C6.2@4095.37,1007.6 C7.2@4136.5,1007.6 ; C7.2@4137.08,1008.19 4181.39,1008.19 v1@4181.61,1007.97
  Top Layer w30: v1(1680.47,1175.49) 1714.51,1175.49 v1(1715,1175) v1(2595,1175) 2625.52,1175 v1(2625.78,1175.26)
  Middle Layer w20: v1(3137.8,1096.12) 3137.8,1095.14 3122.05,1079.39 3122.05,866.14 3173.23,814.96 3291.34,696.85 ; v1(4045,1515) 4043.16,1513.16 4033.08,1513.16 4011.81,1491.89 4011.81,1423.44 ; v1(4079.67,1423.44) 4011.81,1423.44 ; v1(4182.14,1008.07) 4101.63,1008.07 4011.81,1097.89 4011.81,1423.44
  Middle Layer w22: 3173.23,814.96 3409.45,814.96 ; 3291.34,696.85 3358.27,629.92 3657.48,629.92 3775.59,748.03 v1(3842.52,748.03) 3893.7,799.21 v1(3893.7,830.71) ; v1@3440.51,814.96 3409.45,814.96 ; v1(3440.94,814.96) 3409.45,814.96
  Middle Layer w30: v1(2595,1175) 3117.43,1175 v1@3135,1157.43 ; v1(3133.59,1182.79) 3135,1181.38 v1@3135,1157.43 ; v1(3135,1155) v1@3135,1157.43
  Middle Layer w50: H24.2@268,884 264.54,884 257.57,877.02 257.57,873.57 141,757 141,414.7 241.7,314 1162.15,314 1325,476.85 1325,717 1568,960 1568,1119 1624.49,1175.49 v1(1680.47,1175.49) 1714.51,1175.49 v1(1715,1175)
  Bottom Layer w10: v1(3010,1540) 3060,1490 v1(3160,1490)
VDD_SENSORS: C24.2 H25.2 R47.1 R48.1 R50.1 R53.1 R54.1 R55.1 R56.1 R61.1 R82.1 R85.1 U1.8 | length 9042.1
  Top Layer w10: v1@2845.2,1493.38 R85.1@2897.64,1493.38 R82.1@2937.01,1493.38 ; v1(3326.77,984.25) 3370.08,984.25 3386.5,967.83 3386.5,958.07 3389.76,954.8 3328.62,954.8 U1.8@3328.54,954.72 ; R47.1@4583.66,875 v1(5410,875) 5460,825 5671.46,825 5709.05,862.6 R50.1@5709.05,897.24 ; v1(5410,1320) 5410,1352.8 5417.2,1360 R48.1@5417.68,1360
  Top Layer w23.62: R56.1@1604.33,1362.2 R56.1@1608.27,1358.27 ; 1608.27,1240.16 2330.71,1240.16 2389.76,1299.21 2389.76,1338.58 R54.1@2423.23,1372.05 ; v1(2842.23,1466.59) 2842.52,1466.88 v1(2842.52,1496.06) 2842.52,1588.58 R61.1@3094.49,1840.55 3238.19,1840.55 3274.45,1876.81 4116.81,1876.81 v1(4135,1895) 4160.79,1895 v1(4161.89,1893.9) ; v1(4525,905) 4525,895 4545,875 4577.76,875 R47.1@4580.71,872.05 R47.1@4583.66,875 ; R50.1@5709.05,897.24 5709.45,897.64 R50.1@5710.24,897.64
  Top Layer w30: R54.1@2423.23,1372.05 v1@2477.95,1372.05 ; v1(2480.74,1368.61) 2480.74,1368.42 v1(2499.09,1350.07)
  Top Layer w40: H25.2@1008,885 1436.18,885 1481.3,930.12 1545,930.12 ; R53.1@1604.33,877.95 1547.95,877.95 1545,875 1545,930.12 ; R56.1@1604.33,1362.2 1584.14,1362.2 1546.84,1399.51 1546.84,1766.09 R55.1@1608.27,1827.52 ; R56.1@1608.27,1358.27 1604.33,1354.33 1604.33,1053.15 1545,993.82 1545,930.12
  Middle Layer w10: v1(5410,875) v1(5410,1320)
  Middle Layer w23.62: v1@2500,1350 2500,1299.21 ; v1(2842.23,1466.59) 2842.23,1495.77 v1(2842.52,1496.06) ; v1@2842.52,1466.59 2842.52,1330.71 2807.09,1295.28 2503.94,1295.28 2500,1299.21 ; v1(3019.69,1023.62) 2938.31,1105 2605,1105 2500,1210 2500,1299.21 ; v1(4135,1895) v1@4161.89,1895 ; v1(4161.89,1893.9) 4180.79,1875 4290.35,1875 4500,1665.35 4500,930 v1(4525,905)
  Middle Layer w30: v1(2480.74,1368.61) 2499.35,1350 v1@2500,1350
  Bottom Layer w23.62: v1(3019.69,1023.62) 3059.06,984.25 v1(3326.77,984.25) ; v1@4161.42,1894.37 v1(4161.89,1893.9)
VDD_SENSORS_ACC: C37.2 C38.2 R53.2 U3.5 U3.12 U3.13 U3.14 | length 1434.7
  Top Layer w12: 2180,880.95 2180.95,880 ; 2293,849 2293,824 2326,791 2391,791 2466.23,866.23 2466.23,1043.23 2444.47,1065 2401,1065 2391,1055 U3.12@2366.61,1055 2366.61,1073.56 2359.58,1080.59 U3.14@2321.33,1080.59 ; C37.2@2321.33,896.32 U3.5@2321.33,930.98
  Top Layer w23.62: R53.2@1604.33,937.01 1611.22,930.12 1644.88,930.12 1695,880 2180.95,880 2206,880 2237,849 2293,849 C38.2@2328,849 C37.2@2328,888
VFEM_ADC: IC1.17 R35.2 R36.1 | length 612.8
  Top Layer w10: R36.1@3059.06,1191.66 3059.06,1134.56 3064.06,1129.56 3091.79,1129.56 v1(3094.4,1126.96) ; IC1.17@3409.92,1161.42 3467.89,1161.42 3486.12,1143.19 v1(3487.58,1143.19)
  Bottom Layer w10: v1(3094.4,1126.96) 3164.38,1126.96 3193.25,1098.08 3456.35,1098.08 3478.64,1120.38 3478.64,1120.55 3485.47,1127.38 3485.47,1141.08 v1(3487.58,1143.19)
VFEM_SHUNT_TOGGLE: IC1.86 R36.2 | length 1005.8
  Top Layer w10: R36.2@3059.06,1225.66 3082.85,1225.66 3095,1213.51 v1(3095,1210) ; IC1.86@3753.94,1544.8 3753.94,1443.87 3769.48,1428.32 v1(3769.48,1424.63)
  Bottom Layer w10: v1(3095,1210) 3097.61,1212.61 3105.28,1212.61 3107.67,1215 3652.65,1215 3790,1352.35 3790,1404.12 v1(3769.48,1424.63)
VIN: C42.2 C44.2 C49.1 H17.2 R10.2 R68.1 R74.1 U6.1 U6.10 U8.10 | length 2113.4
  Top Layer w10: R68.1@79.29,2057.01 79.29,2119.14 85.15,2125 219.14,2125 225,2119.14 225,2080.98 C42.2@230.87,2075.12 230.87,2045.87 214.06,2029.06 214.06,2016.14 213.98,2016.06 U6.10@201.34,2016.06 ; R74.1@402.32,2050.31 402.32,2119.32 416,2133 530.63,2133 546.99,2116.64 554.49,2109.14 554.49,2073.67 C44.2@557.83,2070.32 547.09,2059.57 547.09,2041.74 529.49,2024.14 529.49,2009.45 529.41,2009.37 U8.10@520.43,2009.37 ; 532.47,2203.47 R10.2@557.25,2203.47
  Top Layer w15: R68.1@79.29,2057.01 79.29,2056.22 84,2051.52 96.05,2051.52 U6.1@129.57,2018
  Middle Layer w50: v1(318.6,2218.57) 318.6,2229.46 318.36,2229.7 318.36,2278.04 v1(318.84,2278.51) 318.84,2593.84 412.87,2687.87 H17.2@566.93,2687.87
  Bottom Layer w50: v1(318.6,2218.57) 318.6,2229.46 318.36,2229.7 318.36,2278.04 v1(318.84,2278.51) 318.84,2593.84 412.87,2687.87 H17.2@566.93,2687.87
  other v1: 318.36,2248.42
pads on no net: FID1.1 FID2.1 FID3.1 H5.15 IC2.1 IC2.2 IC2.3 IC2.4 IC2.6 IC2.9 IC2.10 IC2.14 IC2.18 IC2.20 J3.A2 J3.A3 J3.A8 J3.A10 J3.A11 J3.B2 J3.B3 J3.B8 J3.B10 J3.B11 M1.1 M2.1 M3.1 M4.1 MH1.1 MH2.1 U2.6 U3.1 U3.2 U3.15 U3.17 U3.18 U3.19 U3.20 U3.21 U3.22 U3.23 U3.24 U7.1 U7.2 U7.3 U7.7 U7.9 U7.10 U7.11 U7.14 U7.16 U7.17 U7.18 U7.19 U7.20 U7.21 U7.23 U7.25 U7.28 U7.32

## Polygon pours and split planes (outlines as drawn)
GND on Top Layer "Top_GND" (solid, remove dead copper, pour order 18): 3.94,3188.98 3.94,3325.2 cw(c103.94,3325.2) 103.94,3425.2 5927.56,3425.2 cw(c5927.56,3325.2) 6027.56,3325.2 6027.56,100 cw(c5927.56,100) 5927.56,0 103.94,0 cw(c103.94,100) 3.94,100 3.94,275.59
VIN on Top Layer "VIN_L01_P006" (solid, pour order 6): 214.51,2297.59 214.51,2056.37 246.7,2056.37 246.7,2076.7 285,2115 516.34,2115 541.77,2089.58 541.77,2053.8 572.98,2053.8 595,2075.82 595,2160 457.41,2297.59
BAT_VIN on Top Layer "BAT_VIN_L01_P009" (solid, pour order 9): 517.24,2631.02 517.24,2552.76 530,2540 555,2540 600,2495 600,2400 580,2380 580,2365 585,2360 659.36,2360 765,2465.64 765,2523.5 658.5,2630 600,2630
BAT_POS on Top Layer "BAT_POS_L01_P008" (solid, pour order 8): 125,2420 223.51,2321.49 566.49,2321.49 580,2335 570,2345 570,2421.64 585,2436.64 585,2475 550,2510 290,2510 255,2545 135,2545 125,2535
4V3 on Top Layer "NONET_L-01_P-001" (solid, pour order 10): 503.06,1925.59 503.19,1925.59 553.7,1846.47 553.7,1809.14 602.38,1809.14 602.38,1872.17 580.06,1894.48 565.66,1894.48 559.49,1900.65 559.49,1913.92 538.21,1935.19 511.15,1935.19 508.88,1932.92
VIN on Top Layer "NONET_L-01_P-001" (solid, pour order 11): 502.68,2011.86 502.68,2016.04 542.15,2055.51 542.15,2101.97 542.35,2102.17 563.25,2102.17 574.01,2091.42 574.01,2053.8 538.17,2017.96 538.17,2012.82
3V3 on Top Layer "NONET_L-01_P-001" (solid, pour order 14): 183.63,1932.19 183.63,1931.45 189.85,1925.23 198.17,1918.09 222.28,1848.56 222.28,1830 259.02,1830 259.02,1902.35 242.75,1915.54 242.75,1930.24 230.84,1942.14 193.74,1942.14 183.93,1932.33
VIN on Top Layer "NONET_L-01_P-001" (solid, pour order 15): 184.15,2016.73 184.15,2025.69 215.51,2057.05 215.51,2090.83 246.01,2090.83 246.7,2090.14 246.7,2054.12 245,2050 240.84,2038.71 218.69,2016.56 183.98,2016.56
VDD_MCU on Top Layer "VDD_MCU_L01_P017" (solid, pour order 17): 3350.5,1103.9 3377.17,1103.9 3381.09,1107.83 3381.32,1107.61 3436.64,1107.61 3438.66,1105.59 3438.66,1078.54 3436.98,1076.86 3378.18,1076.86 3372.79,1082.25 3350.28,1082.25
VDD_MCU on Top Layer "NONET_L-01_P-001" (solid, pour order 16): 3390,1570 3478.76,1570 3484.07,1564.69 3483.91,1564.52 3483.91,1519.91 3417.07,1519.91 3390,1546.98
GND on Bottom Layer "GND_L04_P005" (solid, remove dead copper, pour order 5): 3.94,3188.98 3.94,3325.2 cw(c103.94,3325.2) 103.94,3425.2 5927.56,3425.2 cw(c5927.56,3325.2) 6027.56,3325.2 6027.56,100 cw(c5927.56,100) 5927.56,0 103.94,0 cw(c103.94,100) 3.94,100 3.94,275.59
GND on Middle Layer "GND_L03_P007" (solid, remove dead copper, pour order 7): 3.94,3188.98 3.94,3325.2 cw(c103.94,3325.2) 103.94,3425.2 5927.56,3425.2 cw(c5927.56,3325.2) 6027.56,3325.2 6027.56,100 cw(c5927.56,100) 5927.56,0 103.94,0 cw(c103.94,100) 3.94,100 3.94,275.59
GND on Ground Plane (split plane): 5950.87,3402.03 5965.41,3396.01 5978.49,3387.26 5989.62,3376.13 5998.37,3363.05 6004.39,3348.5 6007.46,3333.07 6007.46,3325.2 6007.46,2317.93 5827.89,2317.93 5826.71,2320.15 5824.21,2323.19 5818.67,2328.73 5815.62,2331.23 5814.01,2332.1 5812.15,2333.09 5804.91,2336.09 5801.14,2337.23 5797.22,2337.62 5789.39,2337.62 5785.47,2337.23 5782.04,2336.19 5781.7,2336.09 5774.47,2333.09 5770.99,2331.23 5767.95,2328.73 5762.41,2323.2 5759.91,2320.15 5759.05,2318.53 5758.05,2316.68 5755.06,2309.44 5754.76,2308.47 5753.91,2305.67 5753.73,2303.86 5753.53,2301.75 5753.53,2297.83 5753.53,2186.25 5625,2186.25 5625,2186.13 5618.4,2186.13 5614.33,2187.69 5611.14,2189.28 5608.16,2192.26 5567.79,2151.9 5573.63,2146.26 5580.1,2140.79 5592.42,2133.96 5598.62,2132.22 5605.19,2130.18 5611.14,2129.52 5618.4,2128.92 5625,2128.92 5625,2128.86 5753.53,2129.3 5753.53,2017.13 5753.53,2013.21 5753.91,2009.29 5755.05,2005.52 5758.05,1998.28 5759.91,1994.81 5762.41,1991.76 5767.95,1986.23 5770.99,1983.73 5774.47,1981.87 5781.7,1978.87 5785.47,1977.73 5789.39,1977.34 5797.22,1977.34 5801.14,1977.73 5804.91,1978.87 5812.15,1981.87 5815.62,1983.73 5818.67,1986.23 5824.21,1991.76 5826.7,1994.81 5827.89,1997.03 6007.46,1997.03 6007.46,1838.58 5791.34,1838.58 5791.34,681.1 6007.46,681.1 6007.46,100 6007.46,92.13 6004.39,76.69 5998.37,62.15 5989.62,49.06 5978.49,37.94 5965.41,29.19 5950.87,23.17 5935.43,20.1 103.94,20.1 96.07,20.1 80.63,23.17 66.09,29.19 53,37.93 41.87,49.06 33.13,62.15 27.1,76.69 24.03,92.13 24.03,100 24.03,275.59 24.03,3188.98 24.03,3325.2 24.03,3333.07 27.1,3348.5 33.13,3363.04 41.87,3376.13 53,3387.26 66.09,3396.01 80.63,3402.03 96.07,3405.1 103.94,3405.1 5935.43,3405.1

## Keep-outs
Keep-Out Layer:
  circle w7.87: c5854.33,3251.97 r110.24
  circle w7.87: c5854.33,173.23 r110.24
  circle w7.87: c177.17,173.23 r110.24
  circle w7.87: c173.23,3255.91 r110.24

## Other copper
Top Layer:
  rectangle net VIN: 522.18,2199.8 564.6,2223.57
  rectangle net BAT_VIN: 543.87,2544.22 561.32,2559.1
  rectangle net BAT_VIN: 592.11,2607.86 619.82,2616.84
Ground Plane (plane layer: these items are gaps in the copper):
  lines w40: 2656.62,1573.84 2656.62,1573.84 ; 2656.62,1573.84 2659.26,1573.49 2663.83,1570.75 2666.92,1566.42 2668.02,1561.21 2667.49,1558.6 2667.89,1556.17 2666.63,1551.41 2663.5,1547.6 2659.09,1545.41 2656.62,1545.33 2653.7,1545.03 2648.29,1542.77 2644.16,1538.62 2641.94,1533.2 2641.66,1530.27 2641.66,1440.82 2641.83,1393.72 2642.2,1389.88 2645.14,1382.79 2650.57,1377.35 2657.67,1374.41 2661.51,1374.04 2740.06,1374 2743.9,1374.37 2751.01,1377.31 2756.44,1382.74 2759.39,1389.84 2759.77,1393.68 2759.77,1530.27 ; 2656.62,1573.84 2621.97,1573.84 2617.9,1573.84 2614.8,1573.84 2609.06,1571.46 2604.66,1567.07 2602.29,1561.33 2602.29,1558.22 2602.29,1354.38 2602.29,1350.46 2605.29,1343.23 2610.82,1337.69 2618.06,1334.69 2621.98,1334.69 2779.45,1334.68 2779.45,1334.65 2783.37,1334.65 2790.6,1337.64 2796.14,1343.18 2799.14,1350.42 2799.14,1354.33 2799.14,1551.21 2799.43,1555.42 2796.75,1563.42 2791.21,1569.79 2783.66,1573.55 2779.45,1573.84 ; 2733.79,1566.58 2733.79,1556.73 2733.79,1554.51 2735.45,1550.4 2738.53,1547.21 2742.58,1545.4 2744.8,1545.33 2747.73,1545.03 2753.13,1542.77 2757.26,1538.62 2759.49,1533.2 2759.77,1530.27 ; 2733.79,1566.58 2733.79,1566.58 ; 2733.79,1566.58 2733.79,1566.58 ; 2733.79,1566.58 2733.79,1568.02 2734.9,1570.69 2736.94,1572.74 2739.61,1573.84 2741.05,1573.84 2779.45,1573.84 ; 2759.77,1530.27 2759.77,1530.27 ; 2779.45,1573.84 2779.45,1573.84 ; 3.94,90.15 3.94,100 3.94,275.59 3.94,3188.98 3.94,3325.2 3.94,3335.05 7.78,3354.37 15.32,3372.56 26.26,3388.94 40.19,3402.87 56.57,3413.82 74.77,3421.35 94.09,3425.2 103.94,3425.2 5937.41,3425.2 5956.73,3421.35 5974.93,3413.82 5991.31,3402.87 6005.23,3388.94 6016.18,3372.56 6023.72,3354.37 6027.56,3335.05 6027.56,3325.2 6027.56,2297.84 5812.99,2297.83 5812.99,2301.75 5810,2308.98 5804.46,2314.52 5797.22,2317.52 5789.39,2317.52 5782.16,2314.52 5776.62,2308.98 5773.62,2301.75 5773.62,2297.83 5773.62,2017.13 5773.62,2013.21 5776.62,2005.97 5782.16,2000.44 5789.39,1997.44 5797.22,1997.44 5804.46,2000.44 5810,2005.97 5812.99,2013.21 5812.99,2017.13 6027.56,2017.13 6027.56,100 6027.56,90.15 6023.72,70.83 6016.18,52.63 6005.23,36.25 5991.31,22.32 5974.93,11.38 5956.73,3.84 5937.41,0 103.94,0 94.09,0 74.77,3.84 56.57,11.38 40.19,22.32 26.26,36.25 15.32,52.63 7.78,70.83 3.94,90.15

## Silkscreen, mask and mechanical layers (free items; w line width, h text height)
Top Overlay:
  circle w10: c5437.44,616.06 r1.1
  circle w10: c780.55,2490.93 r1.49
  circle w10: c440,2055 r1.49
  circle w10: c117.68,2058.23 r1.49
  rectangle: 3706.43,2648.41 3863.99,2675
  lines w7.09: 547.2,2895 547.2,2965 685,2965 685,2895 547.2,2895 ; 1555.12,838.58 1653.54,838.58 1653.54,976.38 1555.12,976.38 1555.12,838.58 ; 1559.06,1318.9 1657.48,1318.9 1657.48,1456.69 1559.06,1456.69 1559.06,1318.9 ; 1559.06,1791.34 1657.48,1791.34 1657.48,1937.01 1559.06,1937.01 1559.06,1791.34 ; 2374.02,1332.68 2472.44,1332.68 2472.44,1470.47 2374.02,1470.47 2374.02,1332.68 ; 3045.28,1801.18 3143.7,1801.18 3143.7,1938.98 3045.28,1938.98 3045.28,1801.18 ; 4374.02,1801.18 4472.44,1801.18 4472.44,1938.98 4374.02,1938.98 4374.02,1801.18 ; 4531.5,832.68 4629.92,832.68 4629.92,970.47 4531.5,970.47 4531.5,832.68 ; 4639.76,1801.18 4838.58,1801.18 4838.58,1988.19 4639.76,1988.19 4639.76,1801.18 ; 5013.78,1801.18 5212.6,1801.18 5212.6,1988.19 5013.78,1988.19 5013.78,1801.18
  lines w7.87: 821.57,1170.54 822.64,1169.47
  lines w10: 316.32,561.1 452.87,697.65 637.87,697.65 ; 316.67,1032.8 453.21,1169.35 ; 454.4,1170.54 821.57,1170.54 ; 636,567.48 636,701.58 636,831.8 ; 636,697.65 821.91,697.65 958,561.55 ; 636.35,1038.9 636.35,1170.54 ; 636.35,1169.35 636.35,1297.24 ; 822.64,1169.47 958.12,1033.99 ; 1107.15,414.93 1107.15,463.93 ; 1257,565.55 1334.03,642.58 ; 1822.83,2657.48 2728.35,2657.48 ; 1925.2,2401.57 1925.2,2909.45 ; 1990.63,950.37 2017.26,977.27 ; 2016.99,976.31 2016.99,1044.89 ; 2017.32,976.3 2082.01,976.3 ; 2027.56,2401.57 2027.56,2909.45 ; 2125.98,2401.57 2125.98,2909.45 ; 2228.35,2401.57 2228.35,2909.45 ; 2322.83,2401.57 2322.83,2909.45 ; 2425.2,2401.57 2425.2,2909.45 ; 2527.56,2401.57 2527.56,2909.45 ; 2625.98,2401.57 2625.98,2909.45 ; 5988.19,856.3 5988.19,169.29 5988.19,114.17 cw(c5913.39,114.17) 5913.39,39.37 5842.52,39.37 5151.57,39.37 ; 5988.19,1732.28 5988.19,1889.76 ; 5988.19,2421.26 5988.19,2511.81 ; 5988.19,2723.83 5988.19,3311.02 ; 5988.19,3303.15 5988.19,3311.02 ; 43.31,1771.65 43.31,3279.53 43.31,3312.02 cw(c117.11,3312.02) 117.11,3385.83 196.85,3385.83 1529.53,3385.83 ; 43.31,1771.65 1529.53,1771.65 ; 43.31,1771.65 43.31,157.48 43.31,118.11 ccw(c122.05,118.11) 122.05,39.37 1529.53,39.37 ; 1529.53,39.37 4501.97,39.37 ; 1529.53,39.37 1529.53,807.09 ; 1529.53,807.09 3015.75,807.09 ; 1529.53,807.09 1529.53,1299.21 ; 1529.53,807.09 4501.97,807.09 ; 1529.53,1299.21 3015.75,1299.21 ; 1529.53,1299.21 2342.52,1299.21 ; 1529.53,1299.21 1529.53,1771.65 ; 1529.53,1771.65 2342.52,1771.65 ; 1529.53,1771.65 3015.75,1771.65 ; 1529.53,1771.65 1529.53,3385.83 ; 1529.53,3385.83 3015.75,3385.83 ; 2342.52,1299.21 2342.52,1771.65 ; 2342.52,1299.21 3015.75,1299.21 ; 2342.52,1299.21 2342.52,1771.65 ; 2342.52,1771.65 3015.75,1771.65 ; 3015.75,807.09 3015.75,1299.21 ; 3015.75,807.09 4501.97,807.09 ; 3015.75,807.09 3015.75,1771.65 ; 3015.75,1299.21 3015.75,1771.65 ; 3015.75,1771.65 3015.75,3385.83 ; 3015.75,1771.65 4501.97,1771.65 ; 3015.75,1771.65 4501.97,1771.65 ; 3015.75,1771.65 3015.75,3385.83 ; 3015.75,3385.83 4501.97,3385.83 ; 4501.97,39.37 5151.57,39.37 ; 4501.97,39.37 4501.97,807.09 ; 4501.97,39.37 4501.97,807.09 ; 4501.97,807.09 5151.57,807.09 5151.57,39.37 ; 4501.97,807.09 5988.19,807.09 5988.19,1771.65 4501.97,1771.65 ; 4501.97,807.09 4501.97,1771.65 ; 4501.97,807.09 4501.97,1771.65 ; 4501.97,1771.65 4501.97,3385.83 ; 4501.97,3385.83 5913.39,3385.83 cw(c5913.39,3311.02) 5988.19,3311.02 ; 1822.83,2401.57 2728.35,2401.57 2728.35,2909.45 1822.83,2909.45 1822.83,2401.57
  text "Wi-Fi HaLow" at 4539.37,3230.17 h118.11
  text "CAMERA" at 1568.9,3228.35 h118.11
  text "MIKROBUS / QWIIC" at 3055.12,3225.36 h118.11
  text "-" at 382.2,3035.09 h200 r90
  text "DEBUG HEADER" at 4730.19,3001.99 h50
  text "+" at 299.62,2864.67 h160
  text "USB" at 618.11,2732.17 h80
  text "3V3" at 2707.17,2685.04 h62.99 r90
  text "RST" at 1907.96,2679.44 h62.99 r90
  text "D1" at 2007.18,2679.44 h62.99 r90
  text "D3" at 2107.1,2679.44 h62.99 r90
  text "D5" at 2206.84,2679.44 h62.99 r90
  text "D7" at 2305.93,2679.44 h62.99 r90
  text "PIXCLK" at 2406.37,2679.44 h62.99 r90
  text "VSYNC" at 2506.81,2679.44 h62.99 r90
  text "SCL" at 2607.25,2679.44 h62.99 r90
  text "QWIIC" at 3649.67,2671.37 h70
  text "-" at 470.85,2654.98 h200 r90
  text "VIN" at 618.11,2632.17 h80
  text "BAT" at 618.11,2535.96 h80
  text "PWDN" at 1906.52,2433.46 h62.99 r90
  text "D0" at 2006.04,2433.47 h62.99 r90
  text "D2" at 2105.43,2433.46 h62.99 r90
  text "D4" at 2204.68,2433.47 h62.99 r90
  text "D6" at 2304.72,2433.47 h62.99 r90
  text "XCLK" at 2405.34,2433.46 h62.99 r90
  text "HYSNC" at 2505.95,2433.46 h62.99 r90
  text "SDA" at 2606.56,2433.47 h62.99 r90
  text "GND" at 2707.17,2433.47 h62.99 r90
  text "+" at 387.5,2389.27 h160
  text "3V3" at 115.27,2104.57 h70.87
  text "4V3" at 439.73,2104.57 h70.87
  text "TX" at 1303.31,2020.75 h50 r90
  text "RX" at 1405.67,2020.75 h50 r90
  text "T_VCC" at 806.85,2016.46 h50 r90
  text "SWCLK" at 906.85,2016.46 h50 r90
  text "SWO" at 1001.89,2016.46 h50 r90
  text "SWDIO" at 1098.59,2016.46 h50 r90
  text "NRST" at 1206.85,2016.46 h50 r90
  text "GND" at 1509.17,2016.46 h50 r90
  text "SDIO" at 4681.1,1927.41 h50
  text "SPI" at 5072.83,1927.41 h50
  text "GND" at 5410.85,1751.23 h50
  text "HOST MCU" at 3047.24,1618.24 h118.11
  text "CURRENT MEASUREMENT" at 77.76,1615.5 h118.11
  text "TEMP." at 2377.95,1615.59 h118.11
  text "BLUETOOTH" at 4551.18,1615.59 h118.11
  text "RGB LED" at 1559.06,1614.17 h118.11
  text "BLE_SCK" at 5157.48,1437.96 h50
  text "BLE_SWCLK" at 4712.6,1335.6 h50
  text "BLE_MOSI" at 5161.42,1335.6 h50
  text "3V3" at 581.06,1318.05 h100 r90
  text "0x44" at 2757.58,1303.15 h90
  text "GND" at 1083.36,1295.46 h50
  text "GND" at 909.36,1294.46 h50
  text "BLE_MISO" at 5161.42,1235.6 h50
  text "BLE_SWDIO" at 4712.6,1233.23 h50
  text "ACCELEROMETER" at 1568.9,1151.71 h118.11
  text "BLE_CS" at 5161.42,1135.6 h50
  text "GND" at 4712.6,1130.52 h50
  text "+Y" at 1987,1077 h53.15
  text "BLE_IRQ" at 5161.42,1035.6 h50
  text "+X" at 2115.79,960.66 h53.15
  text "+Z" at 1920,892 h53.15
  text "MCU" at 204,829.91 h100 r90
  text "0x19" at 2736.99,824.82 h90
  text "HALOW" at 578,769.53 h100 r90
  text "SENSORS" at 1168,723.06 h100 r90
  text "STM32 DEBUG" at 1563.98,657.48 h118.11
  text "BUTTON" at 4543.31,657.48 h118.11
  text "CURR. SENSE" at 5194.14,657.48 h118.11
  text "4V3" at 1258.14,646 h100
  text "4-20mA" at 5618.11,518.39 h100
  text "SENS. I2C" at 2605.1,480.35 h100
  text "SENS. UART" at 2961.01,480.35 h100
  text "DBG UART" at 3305.5,480.35 h100
  text "STM RESET" at 3675.88,480.33 h100
  text "STATUS LEDS" at 4029.04,480.33 h100
  text "SPARE / GPIO" at 1566.88,478.35 h100
  text "SENS. SPI" at 2201.56,478.39 h100
  text "-" at 5355,474.24 h200 r180
  text "GND" at 4932.68,405.56 h50
  text "+" at 5584.78,395 h160 r90
  text "VDDIO" at 578,321.31 h100 r90
  text "VBAT" at 204,308 h100 r90
  text "VFEM" at 970.14,307 h100
  text "CS" at 2503.34,241.47 h50 r90
  text "PA0" at 1853.73,218.09 h50 r90
  text "PA9" at 2048.22,217.63 h50 r90
  text "SCL" at 2652.94,212.73 h50 r90
  text "SCK" at 2208.06,206.54 h50 r90
  text "SDA" at 2756.29,206.63 h50 r90
  text "GND" at 2859.64,204.28 h50 r90
  text "GND" at 3215.93,204.28 h50 r90
  text "GND" at 3566.33,204.28 h50 r90
  text "PC13" at 1751.37,192.91 h50 r90
  text "PA10" at 1948.22,192.91 h50 r90
  text "PD15" at 1656.88,192.04 h50 r90
  text "MOSI" at 2404.91,191.07 h50 r90
  text "MISO" at 2306.49,189.96 h50 r90
  text "DBG_TX" at 3470.21,121.35 h50 r90
  text "DBG_RX" at 3361.25,116.41 h50 r90
  text "SENS_TX" at 3119.82,97.23 h50 r90
  text "SENS_RX" at 3010.86,92.29 h50 r90
  text "MM6108-EKH05 V3" at 332.2,13.53 h118.11
Bottom Overlay:
  lines w10: 1901.57,503.87 3141.73,503.87 ; 1901.57,505 1901.57,799.21 3141.73,799.21
  text "-" at 275,3015 h200 r90
  text "+" at 195,2885.22 h160
  text "-" at 345,2645 h200 r90
  text "+" at 265,2415.22 h160
  text "6V MAX" at 29.08,2410.47 h80 r270
  text "MM6108-EKH05 V3" at 3897.64,846.46 h200
  text "SERIAL:" at 3899.53,499.57 h150
Top Assembly:
  lines w10: 3.94,3188.98 3.94,3324.48 cw(c104.66,3324.48) 104.66,3425.2 240.16,3425.2 1576.38,3425.2 5870.08,3425.2 5926.84,3425.2 cw(c5926.84,3324.48) 6027.56,3324.48 6027.56,3299.21 6027.56,1566.14 ; 3.94,3188.98 3.94,3188.98 ; 3.94,3188.98 3.94,236.22 3.94,94.09 ccw(c98.03,94.09) 98.03,0 240.16,0 2056.3,0 5909.45,0 5926.84,0 ccw(c5926.84,100.72) 6027.56,100.72 6027.56,118.11 6027.56,1566.14 ; 6027.56,1566.14 6027.56,1566.14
